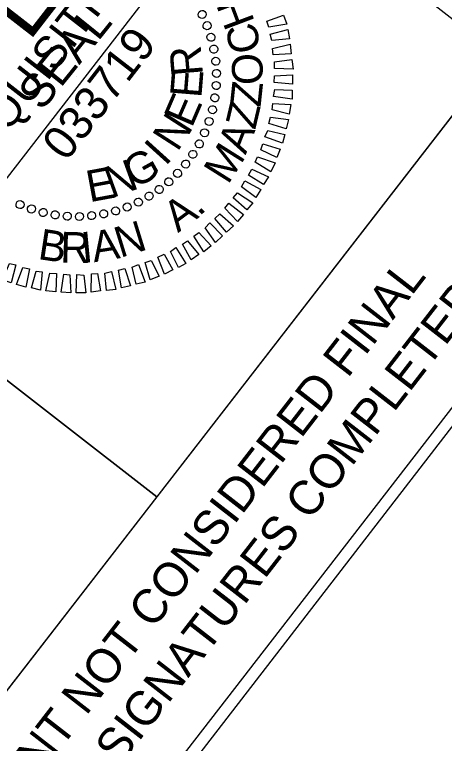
# Model space of a CAD drawing. Extents: x 2013373 to 2015284, y 444589 to 446636.
# Drawn here: x 2014450.7 to 2014527.7, y 446385.3 to 446515.8 of the extents above; entities that cross this region are included whole.
import ezdxf

# ---------------------------------------------------------------- set-up
doc = ezdxf.new("R2010")
doc.units = 0
for name, color, linetype in [('Sheet Clip Boundary CELL', 7, 'Continuous'), ('Sheet Plan And Profile CELL', 7, 'Continuous'), ('Sheet Professional Seal CELL', 7, 'Continuous'), ('Sheet Profile Grid Minor CELL', 7, 'Continuous'), ('Sheet Sticker Exception Certification CELL', 7, 'Continuous'), ('Sheet Sticker Incomplete CELL', 7, 'Continuous')]:
    doc.layers.add(name, color=color, linetype=linetype)

msp = doc.modelspace()

# ---------------------------------------------------------------- linework, layer by layer
at = {"layer": 'Sheet Clip Boundary CELL'}
msp.add_lwpolyline([(2014175.88, 446280.17), (2013513.08, 445427.57), (2013603.78, 445375.37), (2013612.37, 445329.9), (2013915.76, 445258.44), (2014041.96, 445083.42), (2014361.11, 444814.86), (2015247.44, 445957.73), (2014564.17, 446487.44), (2014441.59, 446328.91), (2014350.55, 446399.68), (2014226.85, 446240.55)], close=True, dxfattribs=at)
at = {"layer": 'Sheet Plan And Profile CELL'}
msp.add_line((2014387.32, 446498.4), (2014476.18, 446429.49), dxfattribs=at)
for points in [[(2014387.32, 446498.4), (2014448.6, 446577.42), (2014537.5, 446508.48), (2014476.22, 446429.46)], [(2014326.01, 446419.34), (2014387.32, 446498.4), (2014476.22, 446429.46), (2014414.9, 446350.4)]]:
    msp.add_lwpolyline(points, close=True, dxfattribs=at)
at = {"layer": 'Sheet Professional Seal CELL'}
for p, q in [((2014485.25, 446513.79), (2014485.25, 446513.79)), ((2014485.9, 446511.7), (2014485.9, 446511.7)), ((2014486.46, 446509.56), (2014486.46, 446509.56)), ((2014486.76, 446507.43), (2014486.76, 446507.43)), ((2014486.94, 446505.2), (2014486.94, 446505.2)), ((2014461.81, 446504.7), (2014461.81, 446504.7)), ((2014486.85, 446503.05), (2014486.85, 446503.05)), ((2014486.6, 446500.85), (2014486.6, 446500.85)), ((2014486.19, 446498.69), (2014486.19, 446498.69)), ((2014485.6, 446496.62), (2014485.6, 446496.62)), ((2014484.79, 446494.6), (2014484.79, 446494.6)), ((2014483.75, 446492.61), (2014483.75, 446492.61)), ((2014482.67, 446490.73), (2014482.67, 446490.73)), ((2014481.37, 446488.96), (2014481.37, 446488.96)), ((2014479.9, 446487.31), (2014479.9, 446487.31)), ((2014478.3, 446485.83), (2014478.3, 446485.83)), ((2014476.66, 446484.45), (2014476.66, 446484.45)), ((2014474.82, 446483.22), (2014474.82, 446483.22)), ((2014451.7, 446481.72), (2014451.7, 446481.72)), ((2014472.88, 446482.19), (2014472.88, 446482.19)), ((2014453.73, 446480.91), (2014453.73, 446480.91)), ((2014455.8, 446480.31), (2014455.8, 446480.31)), ((2014468.81, 446480.6), (2014468.81, 446480.6)), ((2014470.9, 446481.26), (2014470.9, 446481.26)), ((2014457.96, 446479.91), (2014457.96, 446479.91)), ((2014460.16, 446479.65), (2014460.16, 446479.65)), ((2014462.31, 446479.57), (2014462.31, 446479.57)), ((2014464.53, 446479.74), (2014464.53, 446479.74)), ((2014466.67, 446480.05), (2014466.67, 446480.05))]:
    msp.add_line(p, q, dxfattribs=at)
for points in [[(2014495.91, 446514.57), (2014498.91, 446515.66), (2014499.47, 446514.02), (2014496.26, 446513.47)], [(2014496.49, 446512.22), (2014499.63, 446513.08), (2014499.98, 446511.41), (2014496.77, 446511.11)], [(2014496.92, 446509.67), (2014500.1, 446510.43), (2014500.25, 446508.74), (2014497.06, 446508.55)], [(2014497.29, 446507.3), (2014500.38, 446507.69), (2014500.59, 446506), (2014497.26, 446506.12)], [(2014497.29, 446504.77), (2014500.51, 446504.99), (2014500.51, 446503.28), (2014497.22, 446503.62)], [(2014497.31, 446502.35), (2014500.46, 446502.24), (2014500.42, 446500.63), (2014497.11, 446501.11)], [(2014496.95, 446499.84), (2014500.22, 446499.65), (2014499.9, 446497.93), (2014496.84, 446498.72)], [(2014496.58, 446497.41), (2014499.78, 446496.95), (2014499.38, 446495.3), (2014496.26, 446496.26)], [(2014496.06, 446495.02), (2014499.15, 446494.27), (2014498.71, 446492.72), (2014495.54, 446493.85)], [(2014495.2, 446492.6), (2014498.27, 446491.67), (2014497.68, 446490.17), (2014494.83, 446491.55)], [(2014494.24, 446490.3), (2014497.37, 446489.2), (2014496.61, 446487.64), (2014493.79, 446489.32)], [(2014493.2, 446488.07), (2014496.22, 446486.74), (2014495.33, 446485.34), (2014492.59, 446487.03)], [(2014491.97, 446485.99), (2014494.83, 446484.46), (2014493.95, 446483), (2014491.35, 446484.95)], [(2014490.63, 446483.86), (2014493.36, 446482.07), (2014492.3, 446480.79), (2014489.86, 446482.94)], [(2014489.12, 446481.99), (2014491.69, 446480), (2014490.64, 446478.73), (2014488.35, 446481.08)], [(2014487.47, 446480.11), (2014489.92, 446477.96), (2014488.67, 446476.84), (2014486.58, 446479.29)], [(2014485.69, 446478.46), (2014487.94, 446476.14), (2014486.73, 446474.99), (2014484.83, 446477.6)], [(2014483.69, 446476.78), (2014485.95, 446474.39), (2014484.59, 446473.3), (2014482.85, 446476.11)], [(2014481.7, 446475.28), (2014483.69, 446472.79), (2014482.35, 446471.87), (2014480.78, 446474.67)], [(2014479.61, 446474.06), (2014481.4, 446471.22), (2014480.07, 446470.48), (2014478.63, 446473.36)], [(2014477.48, 446472.86), (2014479.05, 446470.07), (2014477.55, 446469.27), (2014476.38, 446472.33)], [(2014450.96, 446470.97), (2014450.12, 446467.76), (2014448.56, 446468.28), (2014449.82, 446471.22)], [(2014475.17, 446471.75), (2014476.59, 446468.94), (2014475, 446468.27), (2014474.11, 446471.37)], [(2014453.37, 446470.24), (2014452.75, 446466.99), (2014451.08, 446467.46), (2014452.19, 446470.52)], [(2014455.68, 446469.71), (2014455.35, 446466.43), (2014453.72, 446466.86), (2014454.56, 446469.82)], [(2014468.07, 446469.78), (2014468.87, 446466.57), (2014467.19, 446466.36), (2014466.9, 446469.49)], [(2014470.46, 446470.33), (2014471.5, 446467.19), (2014469.84, 446466.83), (2014469.33, 446470.01)], [(2014472.9, 446471.04), (2014474.12, 446467.87), (2014472.5, 446467.49), (2014471.76, 446470.53)], [(2014458.22, 446469.39), (2014458.09, 446466.13), (2014456.33, 446466.3), (2014457, 446469.45)], [(2014460.63, 446469.16), (2014460.79, 446465.94), (2014459.06, 446466.08), (2014459.51, 446469.27)], [(2014463.09, 446469.15), (2014463.46, 446465.96), (2014461.75, 446465.95), (2014461.87, 446469.21)], [(2014465.59, 446469.43), (2014466.13, 446466.29), (2014464.44, 446466.08), (2014464.5, 446469.33)]]:
    msp.add_lwpolyline(points, close=True, dxfattribs=at)
for centre, major_axis in [((2014484.31, 446515.77), (0.646, 0.318)), ((2014485.19, 446513.77), (0.671, 0.26)), ((2014485.89, 446511.7), (0.691, 0.201)), ((2014486.41, 446509.57), (0.706, 0.14)), ((2014486.74, 446507.41), (0.716, 0.078)), ((2014486.88, 446505.23), (0.72, 0.015)), ((2014486.83, 446503.04), (0.718, -0.048)), ((2014486.59, 446500.86), (0.712, -0.11)), ((2014486.16, 446498.72), (0.699, -0.172)), ((2014485.55, 446496.62), (0.682, -0.232)), ((2014484.75, 446494.58), (0.659, -0.29)), ((2014483.79, 446492.62), (0.631, -0.347)), ((2014482.65, 446490.75), (0.598, -0.4)), ((2014481.35, 446488.99), (0.561, -0.451)), ((2014479.91, 446487.34), (0.52, -0.498)), ((2014478.33, 446485.83), (0.474, -0.542)), ((2014476.62, 446484.46), (0.425, -0.581)), ((2014472.88, 446482.2), (0.318, -0.646)), ((2014474.8, 446483.25), (0.373, -0.616)), ((2014451.69, 446481.75), (-0.29, -0.659)), ((2014453.73, 446480.96), (-0.232, -0.682)), ((2014470.88, 446481.32), (0.26, -0.671)), ((2014455.83, 446480.34), (-0.172, -0.699)), ((2014457.97, 446479.91), (-0.11, -0.712)), ((2014460.15, 446479.67), (-0.048, -0.718)), ((2014462.33, 446479.62), (0.015, -0.72)), ((2014464.52, 446479.77), (0.078, -0.716)), ((2014466.68, 446480.1), (0.14, -0.706)), ((2014468.81, 446480.62), (0.201, -0.691))]:
    msp.add_ellipse(centre, major_axis=major_axis, ratio=0.999708, dxfattribs=at)
at = {"layer": 'Sheet Sticker Exception Certification CELL'}
for p, q in [((2014414.89, 446350.41), (2014537.49, 446508.49)), ((2014562.76, 446488.89), (2014440.16, 446330.81))]:
    msp.add_line(p, q, dxfattribs=at)
at = {"layer": 'Sheet Sticker Incomplete CELL'}
msp.add_lwpolyline([(2014386.73, 446405.85), (2014368.16, 446420.25), (2014458.24, 446536.41), (2014476.81, 446522.01)], close=True, dxfattribs=at)

# ---------------------------------------------------------------- texts
at = {"layer": 'Sheet Professional Seal CELL'}
for s, height, rotation, p in [('SEAL', 5.998, 51.2051, (2014455.59, 446498.32)), ('R', 5.64, 94.6865, (2014484.47, 446504.96)), ('E', 5.64, 85.3292, (2014484.16, 446500.72)), ('E', 5.64, 66.6169, (2014482.45, 446495.33)), ('N', 5.64, 57.2615, (2014479.89, 446491.05)), ('I', 5.64, 47.9063, (2014477.72, 446488.5)), ('G', 5.64, 29.1953, (2014472.2, 446484.49)), ('N', 5.64, 19.8391, (2014468.09, 446482.86)), ('E', 5.64, 10.482, (2014464.12, 446482.15))]:
    msp.add_text(s, height=height, rotation=rotation, dxfattribs=at).set_placement(p)
at = {"layer": 'Sheet Profile Grid Minor CELL'}
for s, height, rotation, p in [('H', 5.5, 110.5529, (2014493.78, 446514.47)), ('033719', 5.998, 52.2051, (2014459.97, 446489.27)), ('C', 5.5, 101.6802, (2014494.9, 446509.42)), ('O', 5.5, 90.9757, (2014495.2, 446503.19)), ('Z', 5.5, 83.8489, (2014494.76, 446499.06)), ('Z', 5.5, 76.7221, (2014493.8, 446495.02)), ('A', 5.5, 68.5363, (2014492.1, 446490.56)), ('M', 5.5, 57.8605, (2014488.95, 446485.19)), ('A', 5.5, 36.4944, (2014479.98, 446476.64)), ('.', 5.5, 44.6802, (2014483.79, 446479.52)), ('N', 5.5, 17.1175, (2014469.64, 446472.2)), ('B', 5.5, 351.358, (2014454.74, 446472.03)), ('R', 5.5, 358.4848, (2014458.85, 446471.4)), ('I', 5.5, 5.4113, (2014462.89, 446471.29)), ('A', 5.5, 8.9317, (2014464.94, 446471.42))]:
    msp.add_text(s, height=height, rotation=rotation, dxfattribs=at).set_placement(p)
at = {"layer": 'Sheet Sticker Exception Certification CELL'}
for s, p in [('DOCUMENT NOT CONSIDERED FINAL', (2014433.14, 446350.97)), ('UNLESS ALL SIGNATURES COMPLETED', (2014437.74, 446340.15))]:
    msp.add_text(s, height=6.124, rotation=52.2051, dxfattribs=at).set_placement(p)
at = {"layer": 'Sheet Sticker Incomplete CELL'}
for s, height, p in [('INCOMPLETE PLANS', 11.52, (2014382.97, 446420.09)), ('DO NOT USE FOR R/W ACQUISITION', 5.76, (2014390.45, 446418.4))]:
    msp.add_text(s, height=height, rotation=52.2051, dxfattribs=at).set_placement(p)

doc.saveas('drawing.dxf')
